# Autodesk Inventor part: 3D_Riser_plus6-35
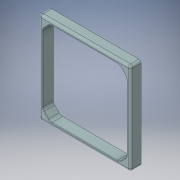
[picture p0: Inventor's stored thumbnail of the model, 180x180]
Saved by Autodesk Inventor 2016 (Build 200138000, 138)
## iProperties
Created: 2016-01
Part Number: 3D_Riser_plus6-35
Material: Generic
Document SubType Name: Modeling
Designer: John
Density: 1 g/cm^3
Appearance: Default
Author: John
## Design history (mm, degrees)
feature "Base1"
sketch "Sketch1"
  geometry: L1 (0, 0)-(180, 0) reference; L2 (185, 5)-(185, 185) reference; L3 (180, 190)-(0, 190) reference; L4 (-5, 185)-(-5, 5) reference; L5 (22.142, 182)-(157.858, 182) reference; L6 (174.071, 169.929)-(164.929, 179.071) reference; L7 (177, 162.858)-(177, 27.142) reference; L8 (164.929, 10.929)-(174.071, 20.071) reference; L9 (157.858, 8)-(22.142, 8) reference; L10 (5.929, 20.071)-(15.071, 10.929) reference; L11 (3, 27.142)-(3, 162.858) reference; L12 (15.071, 179.071)-(5.929, 169.929) reference; C1 r 1.75 at (3, 182) reference; C2 r 1.75 at (177, 8) reference; C3 r 1.75 at (177, 182) reference; C4 r 1.75 at (3, 8) reference; A1 r 5 centre (0, 5) between (-5, 5) and (0, 0) reference; A2 r 5 centre (180, 5) between (180, 0) and (185, 5) reference; A3 r 5 centre (180, 185) between (185, 185) and (180, 190) reference; A4 r 5 centre (0, 185) between (0, 190) and (-5, 185) reference; A5 r 10 centre (157.858, 172) between (164.929, 179.071) and (157.858, 182) reference; A6 r 10 centre (167, 162.858) between (177, 162.858) and (174.071, 169.929) reference; A7 r 10 centre (167, 27.142) between (174.071, 20.071) and (177, 27.142) reference; A8 r 10 centre (157.858, 18) between (157.858, 8) and (164.929, 10.929) reference; A9 r 10 centre (22.142, 18) between (15.071, 10.929) and (22.142, 8) reference; A10 r 10 centre (13, 27.142) between (3, 27.142) and (5.929, 20.071) reference; A11 r 10 centre (13, 162.858) between (5.929, 169.929) and (3, 162.858) reference; A12 r 10 centre (22.142, 172) between (22.142, 182) and (15.071, 179.071) reference; 1 further point
extrude "Extrusion1" join sketch "Sketch1" distance "d0" = 6.35; taper "d1" = 0 deg
sketch "Sketch2"
  geometry: L1 (164.929, 179.071)-(174.071, 169.929) reference; L2 (177, 162.858)-(177, 27.142) reference; L3 (174.071, 20.071)-(164.929, 10.929) reference; L4 (157.858, 8)-(22.142, 8) reference; L5 (15.071, 10.929)-(5.929, 20.071) reference; L6 (3, 27.142)-(3, 162.858) reference; L7 (5.929, 169.929)-(15.071, 179.071) reference; L8 (22.142, 182)-(157.858, 182) reference; L9 (0, 0)-(180, 0) reference; L10 (185, 5)-(185, 185) reference; L11 (180, 190)-(0, 190) reference; L12 (-5, 185)-(-5, 5) reference; C1 r 1.75 at (3, 8) reference; C2 r 1.75 at (177, 182) reference; C3 r 1.75 at (177, 8) reference; C4 r 1.75 at (3, 182) reference; A1 r 10 centre (157.858, 172) between (164.929, 179.071) and (157.858, 182) reference; A2 r 10 centre (167, 162.858) between (177, 162.858) and (174.071, 169.929) reference; A3 r 10 centre (167, 27.142) between (174.071, 20.071) and (177, 27.142) reference; A4 r 10 centre (157.858, 18) between (157.858, 8) and (164.929, 10.929) reference; A5 r 10 centre (22.142, 18) between (15.071, 10.929) and (22.142, 8) reference; A6 r 10 centre (13, 27.142) between (3, 27.142) and (5.929, 20.071) reference; A7 r 10 centre (13, 162.858) between (5.929, 169.929) and (3, 162.858) reference; A8 r 10 centre (22.142, 172) between (22.142, 182) and (15.071, 179.071) reference; A9 r 5 centre (0, 5) between (-5, 5) and (0, 0) reference; A10 r 5 centre (180, 5) between (180, 0) and (185, 5) reference; A11 r 5 centre (180, 185) between (185, 185) and (180, 190) reference; A12 r 5 centre (0, 185) between (0, 190) and (-5, 185) reference; 1 further point
extrude "Extrusion2" join sketch "Sketch2" distance "d2" = 3.175; taper "d3" = 0 deg
body "Solid1"
node "Projected Loop1"
node "Projected Loop2"
